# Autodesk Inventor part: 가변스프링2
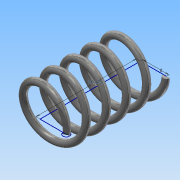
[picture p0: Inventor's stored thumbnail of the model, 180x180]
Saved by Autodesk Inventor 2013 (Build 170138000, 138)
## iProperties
Created: 2018-10
Part Number: 가변스프링2
Material: 스테인리스강
Document SubType Name: Modeling
Designer: Administrator
Density: 8.08 g/cm^3
Mass: 6.29081 g
Surface Area: 15.794 cm^2
Volume: 0.778566 cm^3
Author: Administrator
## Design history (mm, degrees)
sketch "스케치1"
  geometry: L1 (0, 0)-(-8, 0); L2 (-8, 0)-(-8, 30.465); L3 (-8, 30.465)-(0, 30.465); C1 r 1 at (0, 0); 1 further point
  constraints: 6 end point, 1 centre point, 1 coincident, 1 horizontal, 1 parallel, 1 perpendicular, 1 vertical alignment
  dimensions: "d0" = 2 diameter of C1; "d2" = 30.46484 distance of L1.end L2.end (derived); "d3" = 8 distance of L2.end L3.end
feature "코일1" pitch "d4" = 10; turns "d6" = 5; dims "d5" = 30.46484 (= d2), "d7" = 0, angle "d8" = 90 deg, angle "d9" = 90 deg, "d10" = 0, "d11" = 0
sketch "스케치2"
  geometry: C1 r 22.863 at (0, 0); 1 further point
  constraints: 1 centre point, 1 coincident
extrude "돌출1" cut sketch "스케치2" distance "d12" = 10; taper "d13" = 0 deg
node "작업 평면1"
sketch "스케치3"
  geometry: C1 r 28.077 at (-8, 0); 1 further point
  constraints: 1 centre point, 1 coincident
extrude "돌출2" cut sketch "스케치3" distance "d14" = 10; taper "d15" = 0 deg
node "솔리드1"
